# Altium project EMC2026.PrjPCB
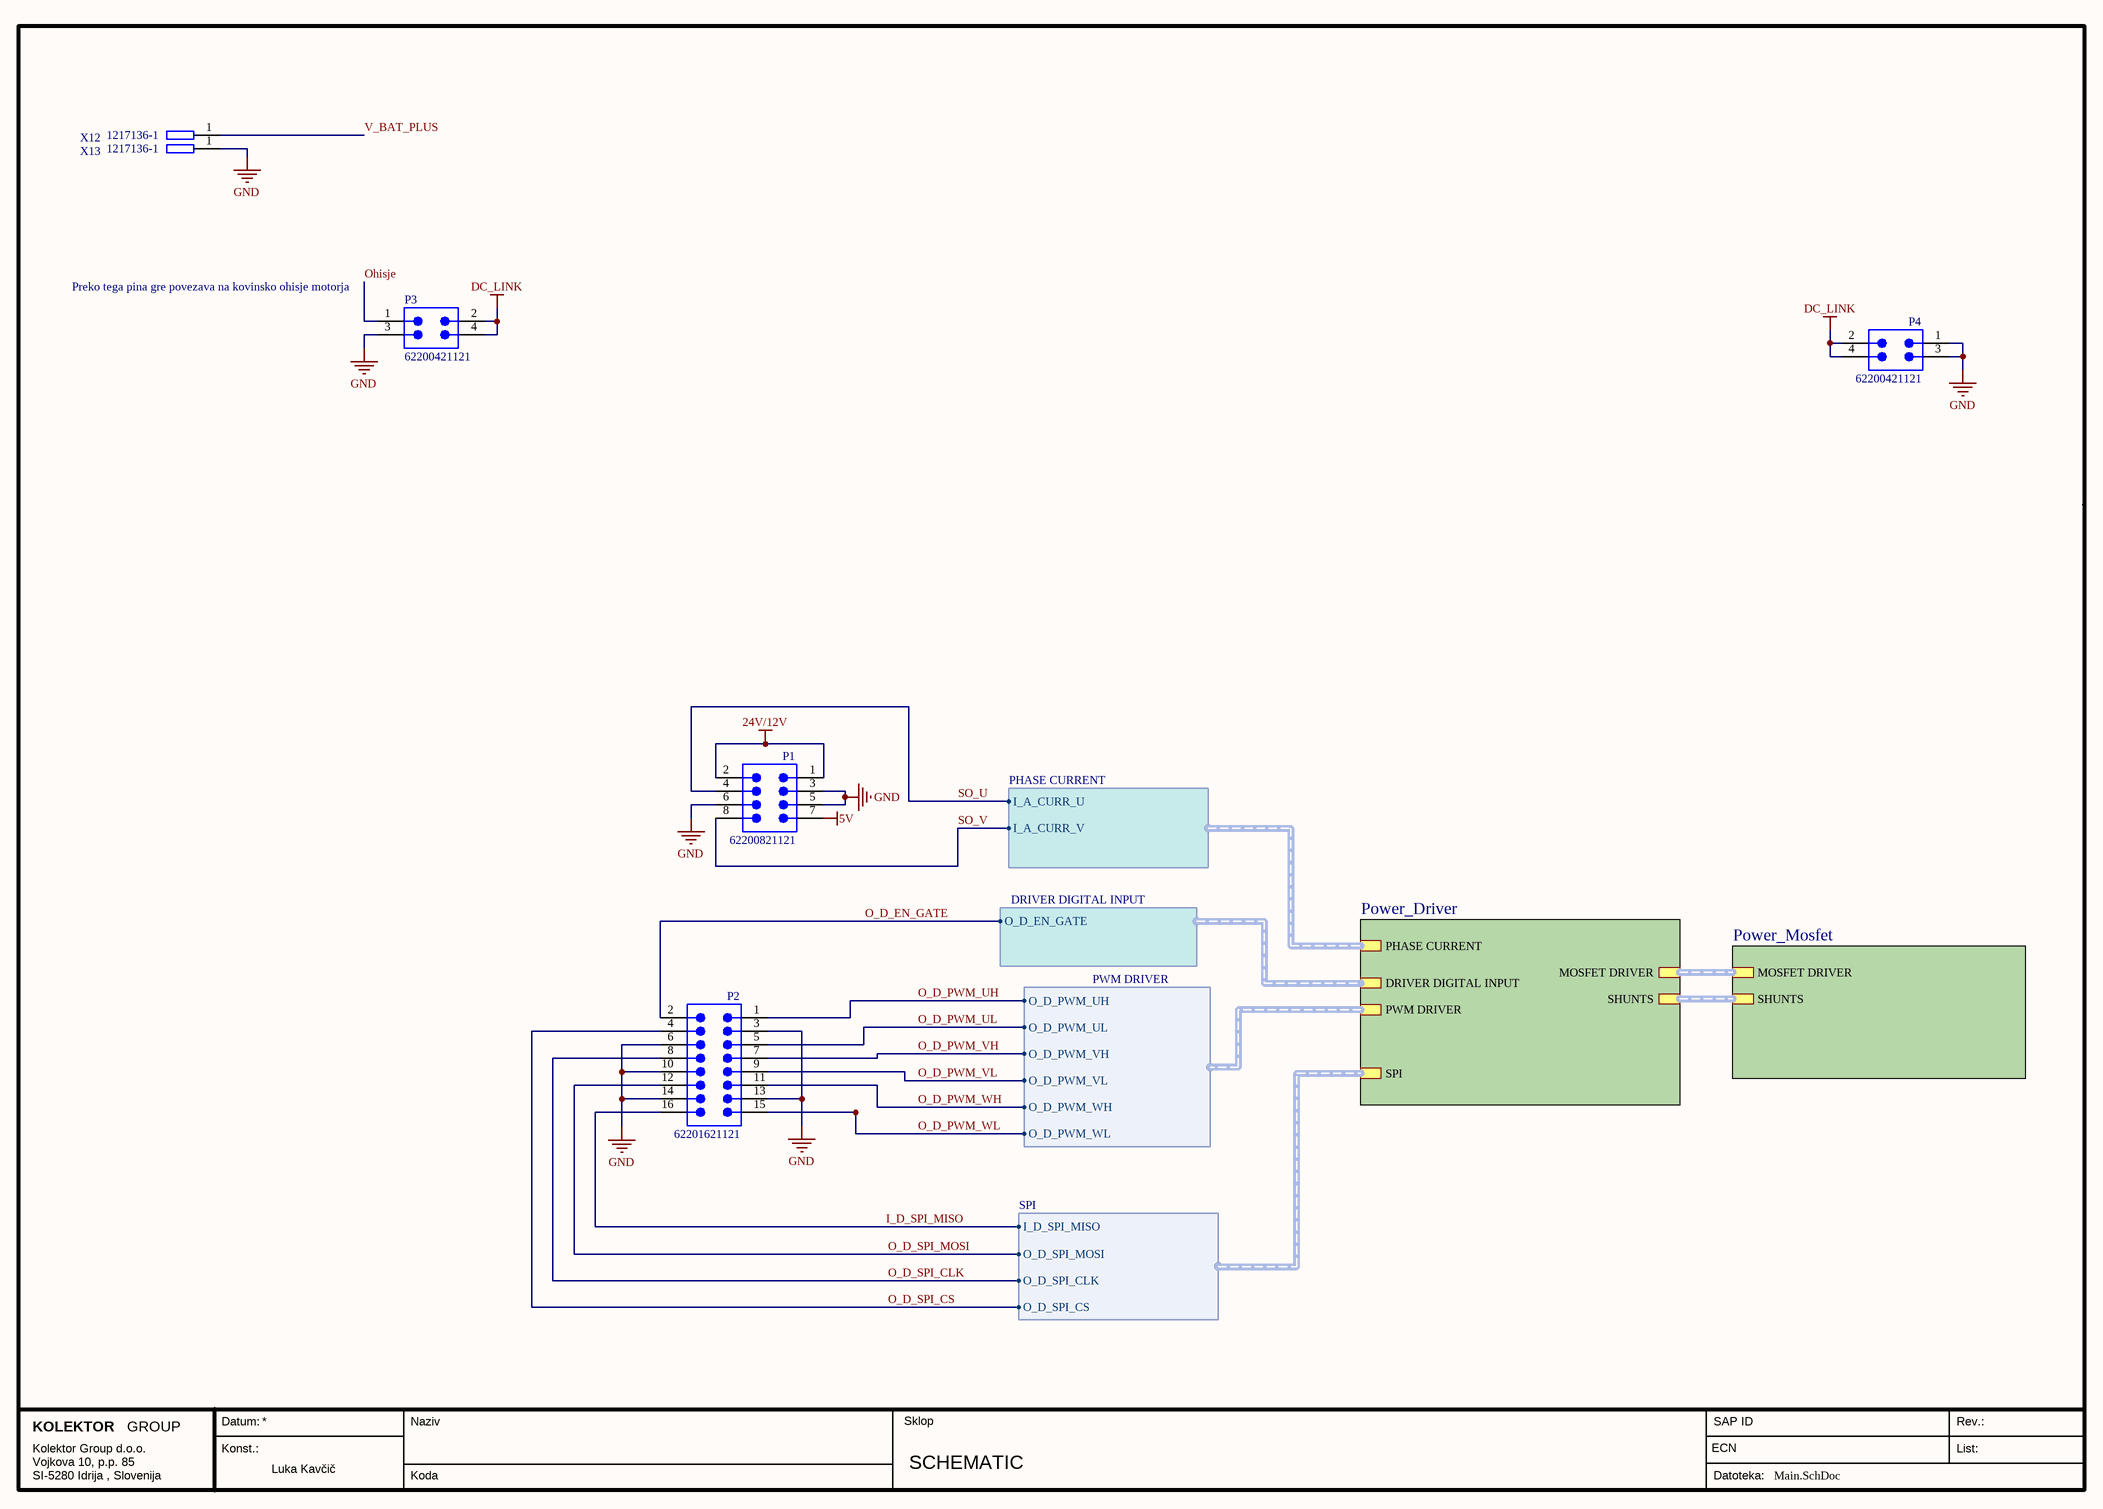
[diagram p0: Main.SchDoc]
Created: Luka Kavčič; PCB_ECN: /; PCB_ID: EMC2026; PCB_Material: FR4; PCB_Rev: 04; PCB_SAP_ID: ******; PCB_SAP_Name: VEZJE TISKANO EMC2026; PCB_Status: in progress
3 sheets, 33 parts. Net scope: hierarchical (ports join the sheet entries above them; power ports are global).
Board file: PCB_top.PcbDoc
Sheets:
  Main.SchDoc
    Power_Driver = Power_Driver.SchDoc
    Power_Mosfet = Power_Mosfet.SchDoc

## Sheet Main.SchDoc
size A3; ApprovedBy: Franci Lahajnar; CheckedBy: Franci Lahajnar; Author: Ciril Močnik; DrawnBy: Ciril Močnik; Engineer: Franci Lahajnar; DocumentNumber: 1; SheetNumber: 1; SheetTotal: 12; PageSetup: Record=PageOptions¦CenterHorizontal=True¦CenterVertical=True¦PrintScale=0.96¦XCorrection=1.00¦YCorrection=1.00¦PrintKind=0¦BorderSize=5000000¦LeftOffset=0¦BottomOffset=0¦Orientation=2¦PaperLength=1000¦PaperWidth=1000¦Scale=100¦PaperSource=7¦PrintQuality=600¦MediaType=1¦DitherType=10¦PrintScaleMode=1¦PaperKind=A4 210 x 297 mm; Sklop: SCHEMATIC; TipDok: SCHEMATIC

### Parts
P1  62200821121  [62200821121]
P2  62201621121  [62201621121]
P3  62200421121  [62200421121]
P4  62200421121  [62200421121]
X12  Manufacturer code: 1217136-1  [FPR_TAB_6.3_P5.08_Pokončni]  (hidden comment: C_TE_FASTON_6.3_P5.08)
X13  Manufacturer code: 1217136-1  [FPR_TAB_6.3_P5.08_Pokončni]  (hidden comment: C_TE_FASTON_6.3_P5.08)

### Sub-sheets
Power_Driver = Power_Driver.SchDoc: MOSFET DRIVER (harness MOSFET DRIVER), DRIVER DIGITAL INPUT (harness DRIVER DIGITAL INPUT), SPI (harness SPI), PHASE CURRENT (harness PHASE CURRENT), SHUNTS (harness SHUNTS), PWM DRIVER (harness PWM DRIVER)
Power_Mosfet = Power_Mosfet.SchDoc: MOSFET DRIVER (harness MOSFET DRIVER), SHUNTS (harness Shunts)

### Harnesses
SPI: I_D_SPI_MISO, O_D_SPI_CLK, O_D_SPI_CS, O_D_SPI_MOSI
PWM DRIVER: O_D_PWM_UH, O_D_PWM_UL, O_D_PWM_VH, O_D_PWM_VL, O_D_PWM_WH, O_D_PWM_WL
DRIVER DIGITAL INPUT: O_D_EN_GATE
PHASE CURRENT: I_A_CURR_U, I_A_CURR_V

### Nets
5V: P1.7
24V/12V: P1.1 P1.2
DC_LINK: P3.2 P3.4 P4.2 P4.4
GND: P1.3 P1.5 P1.6 P2.3 P2.6 P2.10 P2.13 P2.14 P3.3 P4.1 P4.3 X13.1
I_D_SPI_MISO: P2.16 ; sheet Power_Driver/SPI.I_D_SPI_MISO
O_D_EN_GATE: P2.2 ; sheet Power_Driver/DRIVER DIGITAL INPUT.O_D_EN_GATE
O_D_PWM_UH: P2.1 ; sheet Power_Driver/PWM DRIVER.O_D_PWM_UH
O_D_PWM_UL: P2.5 ; sheet Power_Driver/PWM DRIVER.O_D_PWM_UL
O_D_PWM_VH: P2.7 ; sheet Power_Driver/PWM DRIVER.O_D_PWM_VH
O_D_PWM_VL: P2.9 ; sheet Power_Driver/PWM DRIVER.O_D_PWM_VL
O_D_PWM_WH: P2.11 ; sheet Power_Driver/PWM DRIVER.O_D_PWM_WH
O_D_PWM_WL: P2.15 ; sheet Power_Driver/PWM DRIVER.O_D_PWM_WL
O_D_SPI_CLK: P2.8 ; sheet Power_Driver/SPI.O_D_SPI_CLK
O_D_SPI_CS: P2.4 ; sheet Power_Driver/SPI.O_D_SPI_CS
O_D_SPI_MOSI: P2.12 ; sheet Power_Driver/SPI.O_D_SPI_MOSI
Ohisje: P3.1
SO_U: P1.4 ; sheet Power_Driver/PHASE CURRENT.I_A_CURR_U
SO_V: P1.8 ; sheet Power_Driver/PHASE CURRENT.I_A_CURR_V
V_BAT_PLUS: X12.1

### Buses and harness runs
harness sheet Power_Driver/MOSFET DRIVER = sheet Power_Mosfet/MOSFET DRIVER
harness sheet Power_Driver/SHUNTS = sheet Power_Mosfet/SHUNTS

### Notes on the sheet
- (near P3) Preko tega pina gre povezava na kovinsko ohisje motorja

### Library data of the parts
P1 = CMP-1502-00947-4: THT Vertical Pin Header WR-PHD, Pitch 1.27 mm, Dual Row, 8 pins; System: Connector; Row Spacing: 1.27mm; Connector Type: Male Pin; Contact Resistance: 20mΩ; Number of Contacts: 8; Current Rating: 1A; Gender: Male
P2 = CMP-1502-00950-4: THT Vertical Pin Header WR-PHD, Pitch 1.27 mm, Dual Row, 16 pins; Number of Positions: 16; Pitch: 1.27mm; Connector Type: Male Pin; Gender: Male; Current Rating: 1A; Contact Resistance: 20mΩ; System: Connector
P3 P4 = CMP-1502-00946-4: THT Vertical Pin Header WR-PHD, Pitch 1.27 mm, Dual Row, 4 pins; Row Spacing: 1.27mm; Gender: Male; Number of Positions: 4; Contact Resistance: 20mΩ; Current Rating: 1A; System: Connector; Connector Type: Male Pin
X12 X13 = C_TE_FASTON_6.3_P5.08-4: FASTON 6.3 P5.08 Pokončni; Manufacturer: TE CONNECTIVITY; Voltage: /; SAP Ident: 1163972; SAP Name: KONEKTOR 1217136-1 TEC; BS: BS1552; AEC: No; Class: 15526

## Sheet Power_Driver.SchDoc
size A3; CheckedBy: Franci Lahajnar; DrawnBy: Ciril Močnik; DocumentNumber: 5; SheetNumber: 5; SheetTotal: 12; PageSetup: Record=PageOptions¦CenterHorizontal=True¦CenterVertical=True¦PrintScale=0.96¦XCorrection=1.00¦YCorrection=1.00¦PrintKind=0¦BorderSize=5000000¦LeftOffset=0¦BottomOffset=0¦Orientation=2¦PaperLength=1000¦PaperWidth=1000¦Scale=100¦PaperSource=7¦PrintQuality=600¦MediaType=1¦DitherType=10¦PaperKind=A4 210 x 297 mm¦PrintScaleMode=1; Sklop: POWER DRIVER; TipDok: SCHEMATIC
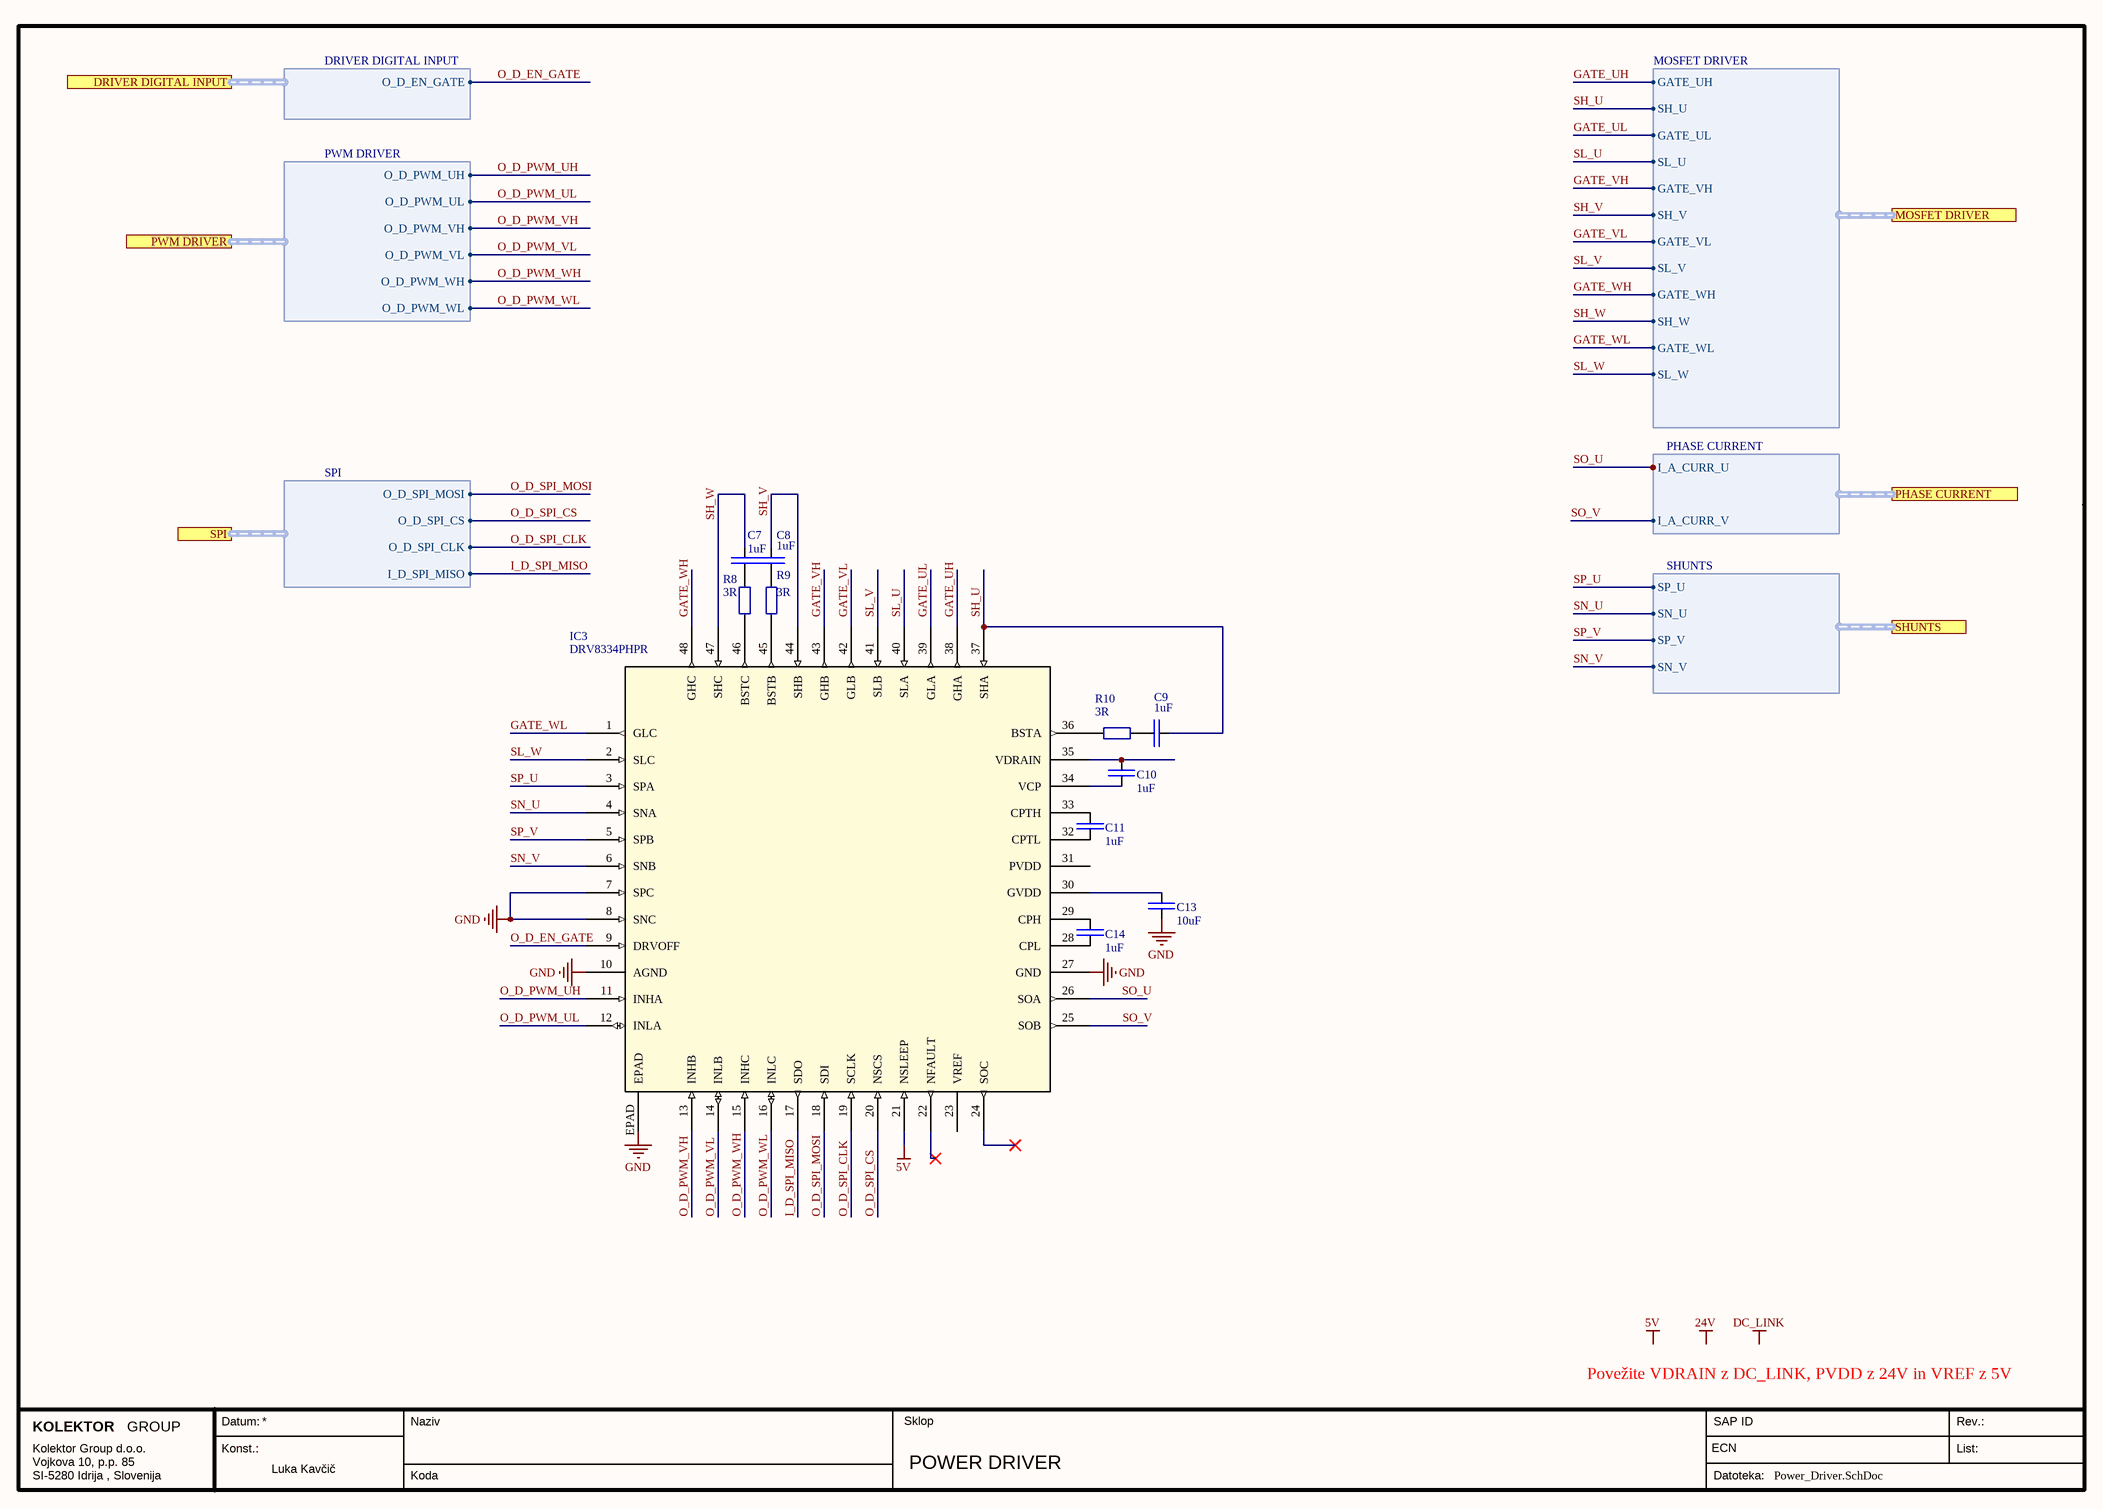
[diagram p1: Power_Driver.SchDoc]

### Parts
C7  HRVal: 1uF  [FPR_0805_C_R0_1]  (hidden comment: C_S_0805_1u_X7R_5)
C8  HRVal: 1uF  [FPR_0805_C_R0_1]  (hidden comment: C_S_0805_1u_X7R_5)
C9  HRVal: 1uF  [FPR_0805_C_R0_1]  (hidden comment: C_S_0805_1u_X7R_5)
C10  HRVal: 1uF  [FPR_0805_C_R0_1]  (hidden comment: C_S_0805_1u_X7R_5)
C11  HRVal: 1uF  [FPR_0805_C_R0_1]  (hidden comment: C_S_0805_1u_X7R_5)
C13  HRVal: 10uF  [FPR_1210_C_R0_10u]  (hidden comment: C_S_1210_10u_X7R_6)
C14  HRVal: 1uF  [FPR_0805_C_R0_1]  (hidden comment: C_S_0805_1u_X7R_5)
IC3  Manufacturer code: DRV8334PHPR  [FPR_HTQFP_48P]  (hidden comment: IC_D_DRV8334PHPR)
R8  HRVal: 3R  [FPR_0603_R_R0_1]  (hidden comment: R_L_0603_3R_1%_1)
R9  HRVal: 3R  [FPR_0603_R_R0_1]  (hidden comment: R_L_0603_3R_1%_1)
R10  HRVal: 3R  [FPR_0603_R_R0_1]  (hidden comment: R_L_0603_3R_1%_1)

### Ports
DRIVER DIGITAL INPUT (harness DRIVER DIGITAL INPUT), MOSFET DRIVER (harness MOSFET DRIVER), PHASE CURRENT (harness PHASE CURRENT), PWM DRIVER (harness PWM DRIVER), SHUNTS (harness SHUNTS), SPI (harness SPI)

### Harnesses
DRIVER DIGITAL INPUT: O_D_EN_GATE
PWM DRIVER: O_D_PWM_UH, O_D_PWM_UL, O_D_PWM_VH, O_D_PWM_VL, O_D_PWM_WH, O_D_PWM_WL
SPI: I_D_SPI_MISO, O_D_SPI_CLK, O_D_SPI_CS, O_D_SPI_MOSI
MOSFET DRIVER: GATE_UH, GATE_UL, GATE_VH, GATE_VL, GATE_WH, GATE_WL, SH_U, SH_V, SH_W, SL_U, SL_V, SL_W
PHASE CURRENT: I_A_CURR_U, I_A_CURR_V
SHUNTS: SP_U, SN_U, SP_V, SN_V

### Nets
5V: IC3.21(NSLEEP)
GND: C13.1 IC3.7(SPC) IC3.8(SNC) IC3.10(AGND) IC3.27(GND) IC3.EPAD
GATE_UH: IC3.38(GHA) ; port MOSFET DRIVER.GATE_UH
GATE_UL: IC3.39(GLA) ; port MOSFET DRIVER.GATE_UL
GATE_VH: IC3.43(GHB) ; port MOSFET DRIVER.GATE_VH
GATE_VL: IC3.42(GLB) ; port MOSFET DRIVER.GATE_VL
GATE_WH: IC3.48(GHC) ; port MOSFET DRIVER.GATE_WH
GATE_WL: IC3.1(GLC) ; port MOSFET DRIVER.GATE_WL
I_D_SPI_MISO: IC3.17(SDO) ; port SPI.I_D_SPI_MISO
O_D_EN_GATE: IC3.9(DRVOFF) ; port DRIVER DIGITAL INPUT.O_D_EN_GATE
O_D_PWM_UH: IC3.11(INHA) ; port PWM DRIVER.O_D_PWM_UH
O_D_PWM_UL: IC3.12(INLA) ; port PWM DRIVER.O_D_PWM_UL
O_D_PWM_VH: IC3.13(INHB) ; port PWM DRIVER.O_D_PWM_VH
O_D_PWM_VL: IC3.14(INLB) ; port PWM DRIVER.O_D_PWM_VL
O_D_PWM_WH: IC3.15(INHC) ; port PWM DRIVER.O_D_PWM_WH
O_D_PWM_WL: IC3.16(INLC) ; port PWM DRIVER.O_D_PWM_WL
O_D_SPI_CLK: IC3.19(SCLK) ; port SPI.O_D_SPI_CLK
O_D_SPI_CS: IC3.20(NSCS) ; port SPI.O_D_SPI_CS
O_D_SPI_MOSI: IC3.18(SDI) ; port SPI.O_D_SPI_MOSI
SH_U: C9.2 IC3.37(SHA) ; port MOSFET DRIVER.SH_U
SH_V: C8.2 IC3.44(SHB) ; port MOSFET DRIVER.SH_V
SH_W: C7.2 IC3.47(SHC) ; port MOSFET DRIVER.SH_W
SL_U: IC3.40(SLA) ; port MOSFET DRIVER.SL_U
SL_V: IC3.41(SLB) ; port MOSFET DRIVER.SL_V
SL_W: IC3.2(SLC) ; port MOSFET DRIVER.SL_W
SN_U: IC3.4(SNA) ; port SHUNTS.SN_U
SN_V: IC3.6(SNB) ; port SHUNTS.SN_V
SO_U: IC3.26(SOA) ; port PHASE CURRENT.I_A_CURR_U
SO_V: IC3.25(SOB) ; port PHASE CURRENT.I_A_CURR_V
SP_U: IC3.3(SPA) ; port SHUNTS.SP_U
SP_V: IC3.5(SPB) ; port SHUNTS.SP_V
NetC7_1: C7.1 R8.2
NetC8_1: C8.1 R9.2
NetC9_1: C9.1 R10.2
NetC10_1: C10.1 IC3.35(VDRAIN)
NetC10_2: C10.2 IC3.34(VCP)
NetC11_1: C11.1 IC3.33(CPTH)
NetC11_2: C11.2 IC3.32(CPTL)
NetC13_2: C13.2 IC3.30(GVDD)
NetC14_1: C14.1 IC3.29(CPH)
NetC14_2: C14.2 IC3.28(CPL)
NetIC3_36: IC3.36(BSTA) R10.1
NetIC3_45: IC3.45(BSTB) R9.1
NetIC3_46: IC3.46(BSTC) R8.1

Not connected (* = marked no-connect by the designer): IC3 22(NFAULT)* 23(VREF) 24(SOC)* 31(PVDD)

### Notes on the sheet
- Povežite VDRAIN z DC_LINK, PVDD z 24V in VREF z 5V
- Labels drawn without touching a wire or pin: 5V, 24V, DC_LINK

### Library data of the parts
C7-C11 C14 = C_S_0805_1u_X7R_5-3: Single capacitor 1uF 10% soft-term AEC200; Manufacturer: Murata; Manufacturer code: GCJ21BR71H105KA01L; SAP Name: KONDENZATOR GCJ21BR71H105KA01L MUR; BS: BS1556; Tolerance: 10; Value [F]: 1e-6; Voltage: 50; SAP Ident: 927197; Class: 15562
C13 = C_S_1210_10u_X7R_6-4: Single capacitor 10uF; Manufacturer: AVX; Manufacturer code: 12105C106K4Z4A; BS: BS1556; SAP Name: KONDENZATOR 12105C106K4Z4A AVX; Tolerance: 10; Value [F]: 10e-6; Voltage: 50; SAP Ident: 919177; Class: 15562; Shelf life: 12 months
IC3 = IC_D_DRV8334PHPR-3: Three phase MOSFET driver; Manufacturer: TI; AEC: No; BS: BS1557; Class: 15571; Output Current: 1000 / 2000 mA; Output Voltage: 60; SAP Ident: 1125019; SAP Name: GONILNIK DRV8334PHPR TI
R8-R10 = R_L_0603_3R_1%_1-3: Upor 3R 0603 1% 100mW; Manufacturer code: CRCW06033R00FKEA; Manufacturer: VISHAY; SAP Name: UPOR CRCW06033R00FKEA VIS; Tolerance: 1; Power: 100e-3; ReleaseDateNum: 45455.4806185648; BS: BS1556; Class: 15561; Value [Ohm]: 3; SAP Ident: 1125027

## Sheet Power_Mosfet.SchDoc
size A3; ApprovedBy: Franci lahajnar; DrawnBy: Ciril Močnik; DocumentNumber: 7; SheetNumber: 7; SheetTotal: 12; PageSetup: Record=PageOptions¦CenterHorizontal=True¦CenterVertical=True¦PrintScale=0.96¦XCorrection=1.00¦YCorrection=1.00¦PrintKind=0¦BorderSize=5000000¦LeftOffset=0¦BottomOffset=0¦Orientation=2¦PaperLength=1000¦PaperWidth=1000¦Scale=100¦PaperSource=7¦PrintQuality=600¦MediaType=1¦DitherType=10¦PaperKind=A4 210 x 297 mm¦PrintScaleMode=1; Sklop: POWER MOSFET BRIDGE; TipDok: SCHEMATIC
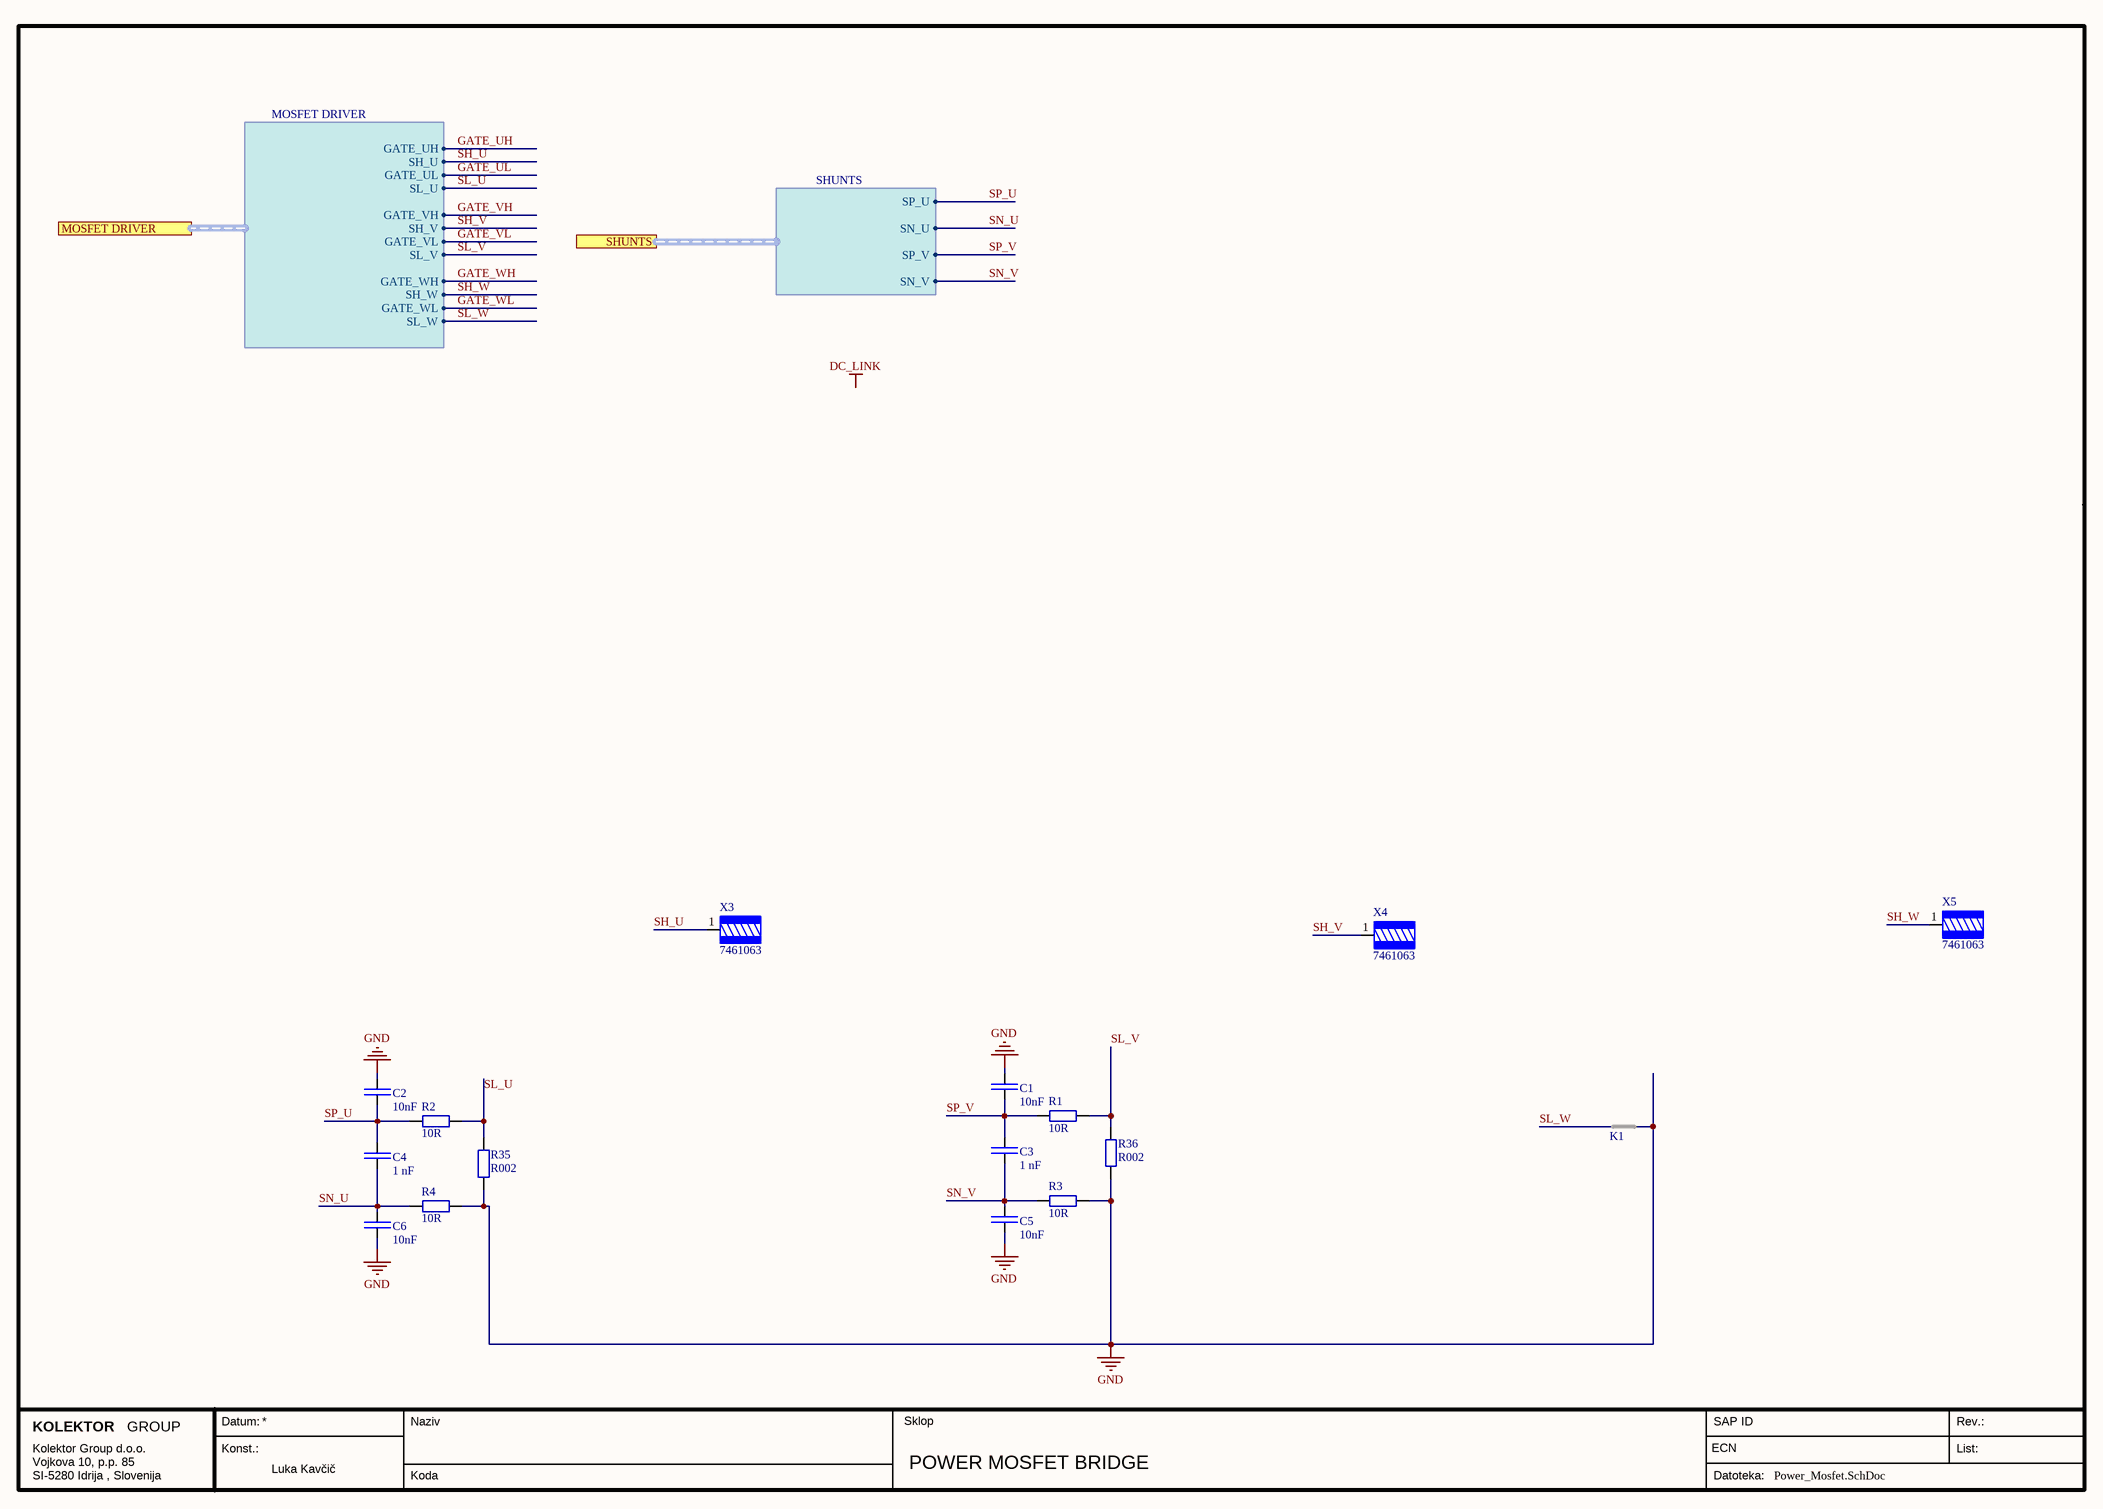
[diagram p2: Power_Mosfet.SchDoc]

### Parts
C1  HRVal: 10nF  [FPR_0603_C_R0]  (hidden comment: C_S_0603_10n_X7R)
C2  HRVal: 10nF  [FPR_0603_C_R0]  (hidden comment: C_S_0603_10n_X7R)
C3  HRVal: 1 nF  [FPR_0603_C_R0]  (hidden comment: C_S_0603_1nF_X7R_3)
C4  HRVal: 1 nF  [FPR_0603_C_R0]  (hidden comment: C_S_0603_1nF_X7R_3)
C5  HRVal: 10nF  [FPR_0603_C_R0]  (hidden comment: C_S_0603_10n_X7R)
C6  HRVal: 10nF  [FPR_0603_C_R0]  (hidden comment: C_S_0603_10n_X7R)
K1  NetTie  [FPR_NETTIE_0_3]  (value not drawn)  (net tie, no BOM)
R1  HRVal: 10R  [FPR_0603_R_R0]  (hidden comment: R_L_0603_10R_1%)
R2  HRVal: 10R  [FPR_0603_R_R0]  (hidden comment: R_L_0603_10R_1%)
R3  HRVal: 10R  [FPR_0603_R_R0]  (hidden comment: R_L_0603_10R_1%)
R4  HRVal: 10R  [FPR_0603_R_R0]  (hidden comment: R_L_0603_10R_1%)
R35  HRVal: R002  [FPR_2512_R_R1]  (hidden comment: R_L_2512_0R002_1%_4)
R36  HRVal: R002  [FPR_2512_R_R1]  (hidden comment: R_L_2512_0R002_1%_4)
X3  Manufacturer code: 7461063  [FPR_K_1P_WURTH]  (hidden comment: K_WURTH_7461063)
X4  Manufacturer code: 7461063  [FPR_K_1P_WURTH]  (hidden comment: K_WURTH_7461063)
X5  Manufacturer code: 7461063  [FPR_K_1P_WURTH]  (hidden comment: K_WURTH_7461063)

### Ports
MOSFET DRIVER (harness MOSFET DRIVER), SHUNTS (harness Shunts)

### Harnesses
SHUNTS: SP_U, SN_U, SP_V, SN_V
MOSFET DRIVER: GATE_UH, GATE_UL, GATE_VH, GATE_VL, GATE_WH, GATE_WL, SH_U, SL_U, SH_V, SL_V, SH_W, SL_W

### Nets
GND: C1.2 C2.2 C5.1 C6.1 K1.1 R3.2 R4.2 R35.1 R36.1
SH_U: X3.1 ; port MOSFET DRIVER.SH_U
SH_V: X4.1 ; port MOSFET DRIVER.SH_V
SH_W: X5.1 ; port MOSFET DRIVER.SH_W
SL_U: R2.2 R35.2 ; port MOSFET DRIVER.SL_U
SL_V: R1.2 R36.2 ; port MOSFET DRIVER.SL_V
SL_W: K1.2 ; port MOSFET DRIVER.SL_W
SN_U: C4.1 C6.2 R4.1 ; port SHUNTS.SN_U
SN_V: C3.1 C5.2 R3.1 ; port SHUNTS.SN_V
SP_U: C2.1 C4.2 R2.1 ; port SHUNTS.SP_U
SP_V: C1.1 C3.2 R1.1 ; port SHUNTS.SP_V

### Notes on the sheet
- Labels drawn without touching a wire or pin: DC_LINK

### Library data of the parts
C1 C2 C5 C6 = C_S_0603_10n_X7R-10: Single capacitor 10 nF; Manufacturer code: 06035C103K4Z4A; Manufacturer: AVX; SAP Name: KONDENZATOR 06035C103K4Z4A AVX; Voltage: 50; BS: BS1556; Class: 15562; Tolerance: 10; Value [F]: 10e-9; SAP Ident: 628870
C3 C4 = C_S_0603_1nF_X7R_3-1: Single capacitor 1nF 5% AEC; Manufacturer code: VJ0603Y102JXAAC; Manufacturer: VISHAY; Tolerance: 5; SAP Name: KONDENZATOR VJ0603Y102JXAAC VIS; Value [F]: 1e-9; Voltage: 50; BS: BS1556; Class: 15562
K1 = NetTie-10: Net tie
R1-R4 = R_L_0603_10R_1%-18: Upor 10R 0603 1% 100mW; Manufacturer: ASJ; Manufacturer code: CR16-10R0-FY; Class: 15561; BS: BS1556; Shelf life: 12 months; SAP Name: UPOR CR16-10R0-FY ASJ; SAP Ident: 220173; Tolerance: 1; Power: 100e-3; Value [Ohm]: 10
R35 R36 = R_L_2512_0R002_1%_4-1: Upor 0R002 2512 1% AEC; Manufacturer code: WSLF25122L000FEA; Manufacturer: VISHAY; SAP Name: UPOR WSLF25122L000FEA VIS; Cat1: 2512; Value [Ohm]: 2e-3; Power: 5; Class: 15561; Tolerance: 1; Shelf life: 24mo; SAP Ident: ******; BS: BS1556
X3-X5 = K_WURTH_7461063-4: Connector POWER Wurth 7461063; Manufacturer: WURTH ELEKTRONIK; UL: /; MaxCurrent: 160; AEC: No; Class: 15526; ReleaseDateNum: 45705.4409943981; Voltage: 300; BS: BS1552; SAP Name: KONEKTOR 7461063 WUE; SAP Ident: 1144983

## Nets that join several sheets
5V: Main (P1.7), Power_Driver (IC3.21)
GND: Main (12 pins), Power_Driver (6 pins), Power_Mosfet (9 pins)
I_D_SPI_MISO: Main (P2.16), Power_Driver (IC3.17)
O_D_EN_GATE: Main (P2.2), Power_Driver (IC3.9)
O_D_PWM_UH: Main (P2.1), Power_Driver (IC3.11)
O_D_PWM_UL: Main (P2.5), Power_Driver (IC3.12)
O_D_PWM_VH: Main (P2.7), Power_Driver (IC3.13)
O_D_PWM_VL: Main (P2.9), Power_Driver (IC3.14)
O_D_PWM_WH: Main (P2.11), Power_Driver (IC3.15)
O_D_PWM_WL: Main (P2.15), Power_Driver (IC3.16)
O_D_SPI_CLK: Main (P2.8), Power_Driver (IC3.19)
O_D_SPI_CS: Main (P2.4), Power_Driver (IC3.20)
O_D_SPI_MOSI: Main (P2.12), Power_Driver (IC3.18)
SH_U: Power_Driver (C9.2 IC3.37), Power_Mosfet (X3.1)
SH_V: Power_Driver (C8.2 IC3.44), Power_Mosfet (X4.1)
SH_W: Power_Driver (C7.2 IC3.47), Power_Mosfet (X5.1)
SL_U: Power_Driver (IC3.40), Power_Mosfet (R2.2 R35.2)
SL_V: Power_Driver (IC3.41), Power_Mosfet (R1.2 R36.2)
SL_W: Power_Driver (IC3.2), Power_Mosfet (K1.2)
SN_U: Power_Driver (IC3.4), Power_Mosfet (C4.1 C6.2 R4.1)
SN_V: Power_Driver (IC3.6), Power_Mosfet (C3.1 C5.2 R3.1)
SO_U: Main (P1.4), Power_Driver (IC3.26)
SO_V: Main (P1.8), Power_Driver (IC3.25)
SP_U: Power_Driver (IC3.3), Power_Mosfet (C2.1 C4.2 R2.1)
SP_V: Power_Driver (IC3.5), Power_Mosfet (C1.1 C3.2 R1.1)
